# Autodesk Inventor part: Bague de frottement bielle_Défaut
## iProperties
Shininess: 64.0
Length Units: 11269
Angle Units: 11279
Time Units: 11290
Mass Units: 11283
Length Display Precision: 3
Angle Display Precision: 2
Compacted: True
Part Number: Bague de frottement bielle_Défaut
Document SubType Name: Modeling
Created: 2006-01
Material: Par défaut
Designer: riri
Density: 0.0
Volumn: 0.0
Area: 0.0
PropertySet Name: Model Information
Control State: 0
Master: False
Checked Out: False
Author: riri
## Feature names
1. Base1
